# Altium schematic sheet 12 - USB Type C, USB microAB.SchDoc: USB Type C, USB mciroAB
size A3; PageSetup: Record=PageOptions¦CenterHorizontal=True¦CenterVertical=True¦PrintScale=0.70¦XCorrection=1.00¦YCorrection=1.00¦PrintKind=0¦BorderSize=5000000¦LeftOffset=0¦BottomOffset=0¦Orientation=2¦PaperLength=4200¦PaperWidth=2970¦Scale=100¦PaperSource=7¦PrintQuality=600¦MediaType=1¦DitherType=10¦PaperKind=A4¦PrintScaleMode=1; Author: Juan Anzola; SheetNumber: 12; SheetTotal: 17
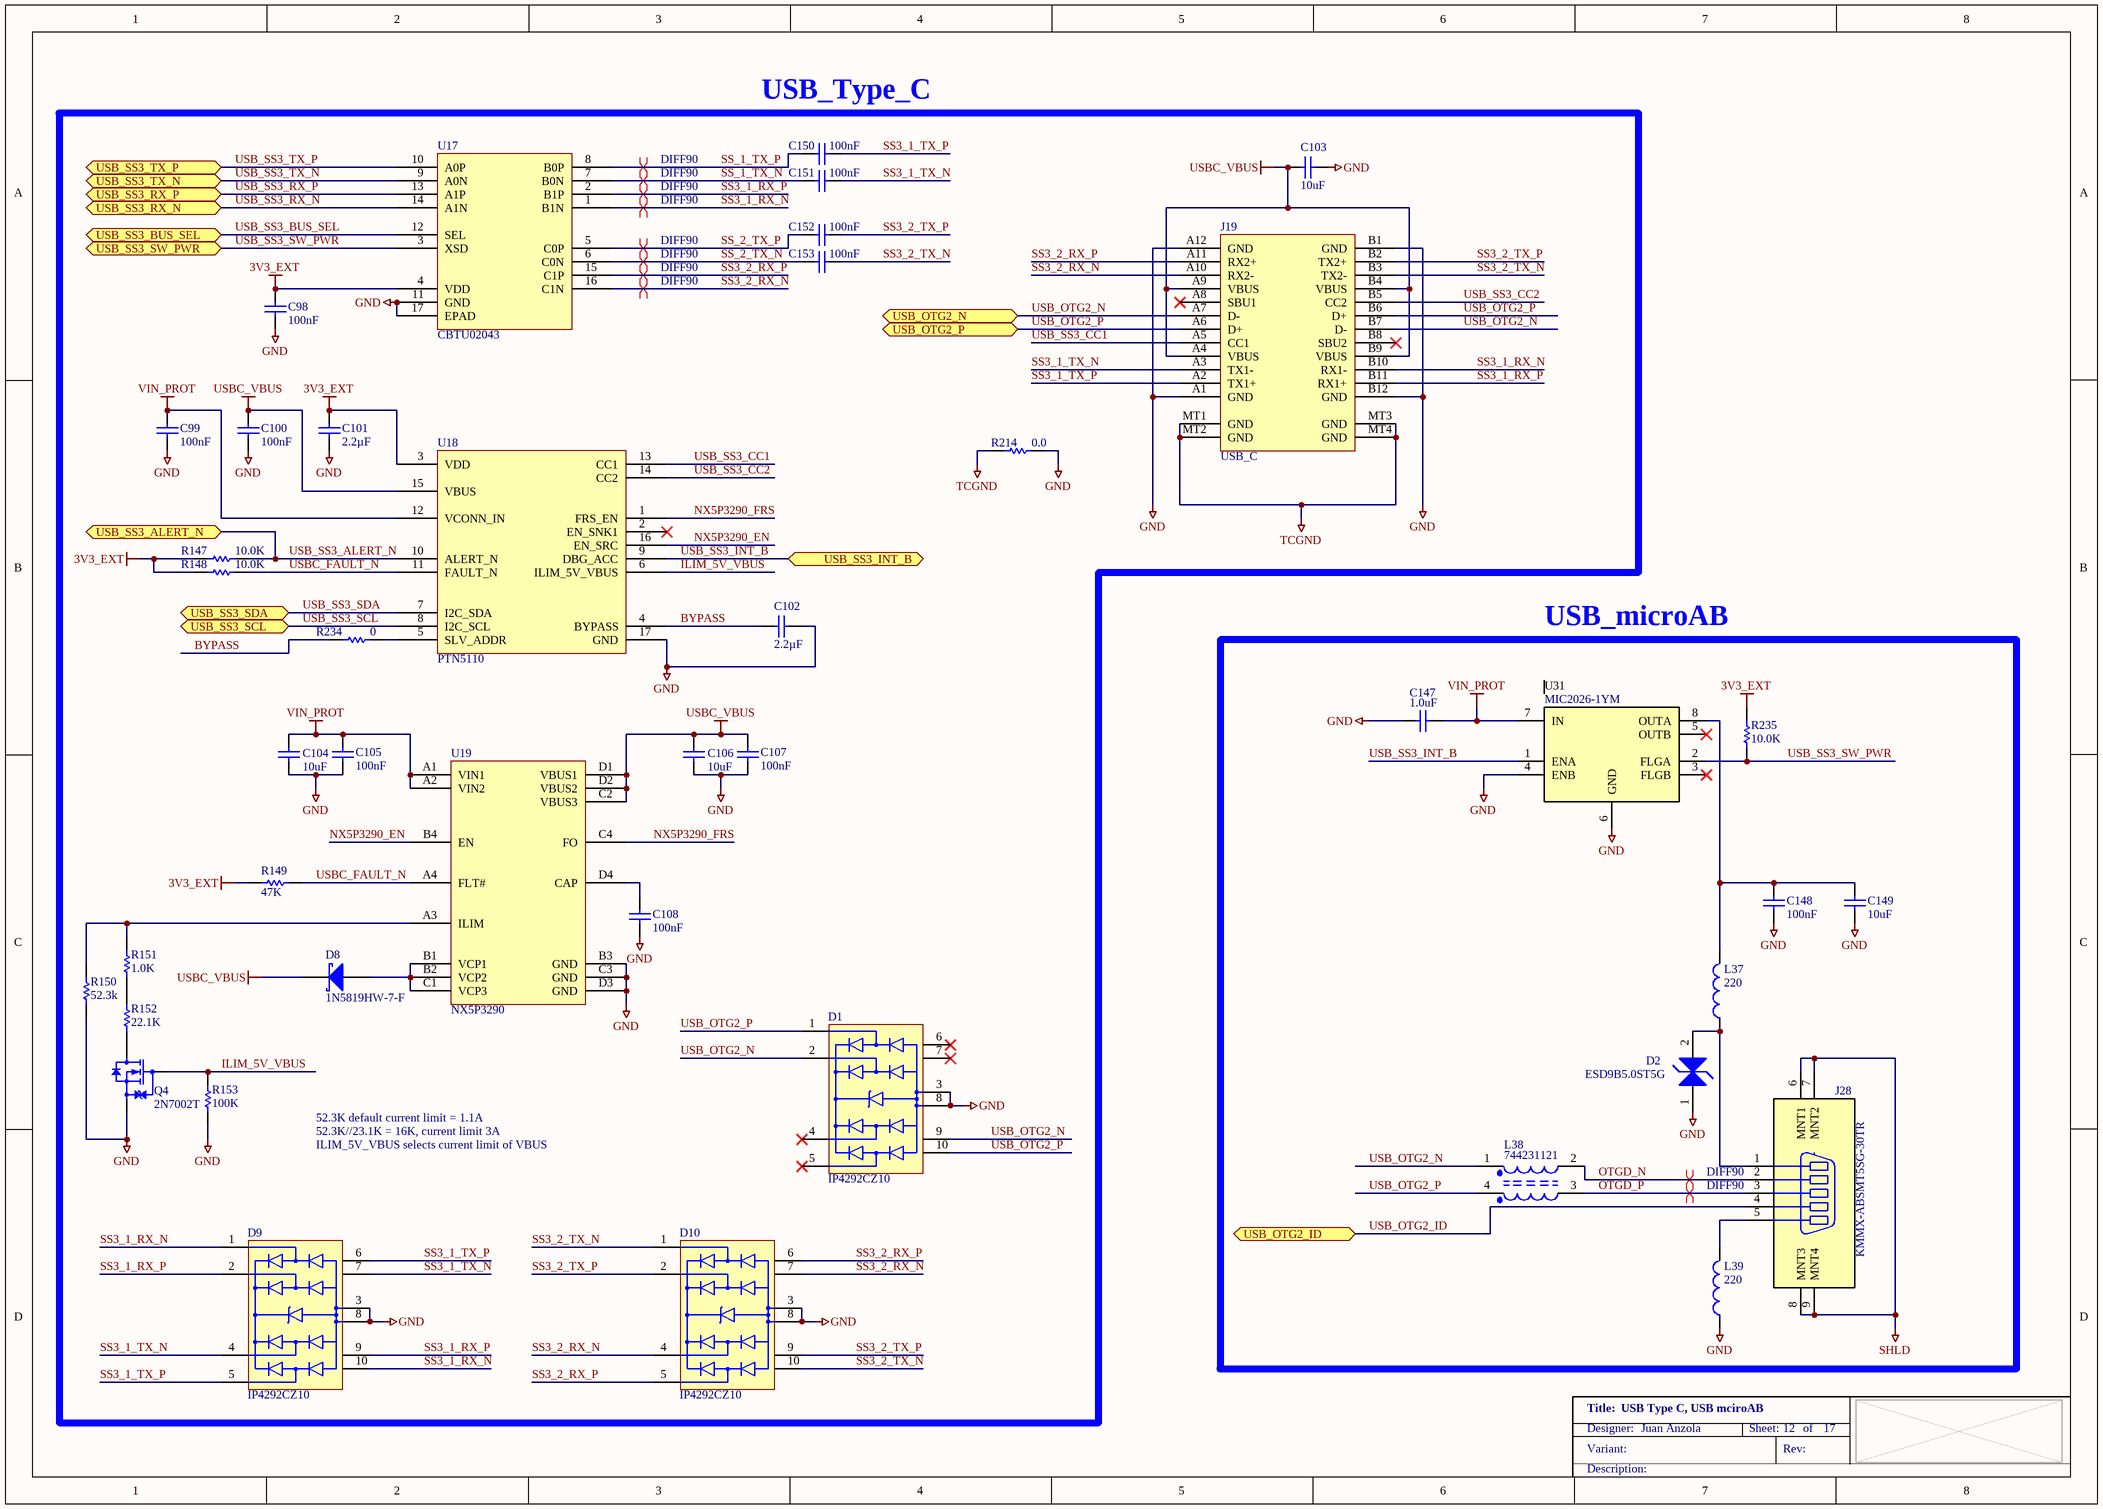
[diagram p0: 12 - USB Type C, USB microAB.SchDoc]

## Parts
C98  100nF  [CAPC1005X55N]
C99  100nF  [CAPC1005X55N]
C100  100nF  [CAPC1005X55N]
C101  2.2µF  [CAPC1005X55L]
C102  2.2µF  [CAPC1005X55L]
C103  10uF  [CAPC1005X55N]
C104  10uF  [CAPC1005X55N]
C105  100nF  [CAPC1005X55N]
C106  10uF  [CAPC1005X55N]
C107  100nF  [CAPC1005X55N]
C108  100nF  [CAPC1005X55N]
C147  1.0uF  [CAPC1005X55N]
C148  100nF  [CAPC1005X55N]
C149  10uF  [CAPC1005X55N]
C150  100nF  [CAPC1005X55N]
C151  100nF  [CAPC1005X55N]
C152  100nF  [CAPC1005X55N]
C153  100nF  [CAPC1005X55N]
D1  IP4292CZ10  [SON50P250X100X50-10N]
D2  ESD9B5.0ST5G  [SODFL1006X43N12]
D8  1N5819HW-7-F  [SOD3716X135N]
D9  IP4292CZ10  [SON50P250X100X50-10N]
D10  IP4292CZ10  [SON50P250X100X50-10N]
J19  USB_C  [MOLEX_201267-0005]
J28  KMMX-ABSMT5SG-30TR  [KYCON_KMMX-ABSMT5]
L37  220  [INDC2013X110N]
L38  744231121  [FIL_DLW21H]
L39  220  [INDC2013X110N]
Q4  2N7002T  [SOTFL50P160X80_GSD-3N]
R147  10.0K  [RESC1005X40N]
R148  10.0K  [RESC1005X40N]
R149  47K  [RESC1005X40N]
R150  52.3k  [RESC1005X40N]
R151  1.0K  [RESC1005X40N]
R152  22.1K  [RESC1005X40N]
R153  100K  [RESC1005X40N]
R214  0.0  [RESC2013X70N]
R234  0  [RESC1005X40N]
R235  10.0K  [RESC1005X40N]
U17  CBTU02043  [PQFN40P160X240X55-17T140X60N]
U18  PTN5110  [QFN40P260X260X40-17T100X110N]
U19  NX5P3290  [BGA16N50P4X4_205X205X59B32N]
U31  Manufacturer_Part_Number: MIC2026-1YM  [SOIC127P600X175-8N]  (hidden comment: MIC2026)

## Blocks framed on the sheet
USB_Type_C: C98-C108 C150-C153 D1 D8-D10 J19 Q4 R147-R153 R214 R234 U17-U19
USB_microAB: C147-C149 D2 J28 L37-L39 R235 U31

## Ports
USB_OTG2_ID (bidir), USB_OTG2_N (bidir), USB_OTG2_P (bidir), USB_SS3_ALERT_N (bidir), USB_SS3_BUS_SEL (bidir), USB_SS3_INT_B (bidir), USB_SS3_RX_N (bidir), USB_SS3_RX_P (bidir), USB_SS3_SCL (bidir), USB_SS3_SDA (bidir), USB_SS3_SW_PWR (bidir), USB_SS3_TX_N (bidir), USB_SS3_TX_P (bidir)

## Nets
3V3_EXT: C98.2 C101.2 R147.1 R148.1 R149.1 R235.2 U17.4(VDD) U18.3(VDD)
GND: C98.1 C99.1 C100.1 C101.1 C102.1 C103.1 C104.1 C105.1 C106.1 C107.1 C108.1 C147.1 C148.1 C149.1 D1.3(GND) D1.8(GND) D2.1 D9.3(GND) D9.8(GND) D10.3(GND) D10.8(GND) J19.A1(GND) J19.A12(GND) J19.B1(GND) J19.B12(GND) L39.1 Q4.S R150.1 R153.1 R214.2 U17.11(GND) U17.17(EPAD) U18.17(GND) U19.B3(GND) U19.C3(GND) U19.D3(GND) U31.4(ENB) U31.6(GND)
SHLD: J28.6(MNT1) J28.7(MNT2) J28.8(MNT3) J28.9(MNT4)
TCGND: J19.MT1(GND) J19.MT2(GND) J19.MT3(GND) J19.MT4(GND) R214.1
USBC_VBUS: C100.2 C103.2 C106.2 C107.2 D8.K J19.A4(VBUS) J19.A9(VBUS) J19.B4(VBUS) J19.B9(VBUS) U18.15(VBUS) U19.C2(VBUS3) U19.D1(VBUS1) U19.D2(VBUS2)
VIN_PROT: C99.2 C104.2 C105.2 C147.2 U18.12(VCONN_IN) U19.A1(VIN1) U19.A2(VIN2) U31.7(IN)
BYPASS: C102.2 R234.2 U18.4(BYPASS)
ILIM_5V_VBUS: Q4.G R153.2 U18.6(ILIM_5V_VBUS)
NX5P3290_EN: U18.16(EN_SRC) U19.B4(EN)
NX5P3290_FRS: U18.1(FRS_EN) U19.C4(FO)
OTGD_N: J28.2 L38.2
OTGD_P: J28.3 L38.3
SS3_1_RX_N: D9.1(CH1) D9.10(NC) J19.B10(RX1-) U17.1(B1N)
SS3_1_RX_P: D9.2(CH2) D9.9(NC) J19.B11(RX1+) U17.2(B1P)
SS3_1_TX_N: C151.2 D9.4(CH3) D9.7(NC) J19.A3(TX1-)
SS3_1_TX_P: C150.2 D9.5(CH4) D9.6(NC) J19.A2(TX1+)
SS3_2_RX_N: D10.4(CH3) D10.7(NC) J19.A10(RX2-) U17.16(C1N)
SS3_2_RX_P: D10.5(CH4) D10.6(NC) J19.A11(RX2+) U17.15(C1P)
SS3_2_TX_N: C153.2 D10.1(CH1) D10.10(NC) J19.B3(TX2-)
SS3_2_TX_P: C152.2 D10.2(CH2) D10.9(NC) J19.B2(TX2+)
SS_1_TX_N: C151.1 U17.7(B0N)
SS_1_TX_P: C150.1 U17.8(B0P)
SS_2_TX_N: C153.1 U17.6(C0N)
SS_2_TX_P: C152.1 U17.5(C0P)
USB_OTG2_ID: J28.4 ; port USB_OTG2_ID
USB_OTG2_N: D1.2(CH2) D1.9(NC) J19.A7(D-) J19.B7(D-) L38.1 ; port USB_OTG2_N
USB_OTG2_P: D1.1(CH1) D1.10(NC) J19.A6(D+) J19.B6(D+) L38.4 ; port USB_OTG2_P
USB_SS3_ALERT_N: R147.2 U18.10(ALERT_N) ; port USB_SS3_ALERT_N
USB_SS3_BUS_SEL: U17.12(SEL) ; port USB_SS3_BUS_SEL
USB_SS3_CC1: J19.A5(CC1) U18.13(CC1)
USB_SS3_CC2: J19.B5(CC2) U18.14(CC2)
USB_SS3_INT_B: U18.9(DBG_ACC) U31.1(ENA) ; port USB_SS3_INT_B
USB_SS3_RX_N: U17.14(A1N) ; port USB_SS3_RX_N
USB_SS3_RX_P: U17.13(A1P) ; port USB_SS3_RX_P
USB_SS3_SCL: U18.8(I2C_SCL) ; port USB_SS3_SCL
USB_SS3_SDA: U18.7(I2C_SDA) ; port USB_SS3_SDA
USB_SS3_SW_PWR: R235.1 U17.3(XSD) U31.2(FLGA) ; port USB_SS3_SW_PWR
USB_SS3_TX_N: U17.9(A0N) ; port USB_SS3_TX_N
USB_SS3_TX_P: U17.10(A0P) ; port USB_SS3_TX_P
USBC_FAULT_N: R148.2 R149.2 U18.11(FAULT_N) U19.A4(FLT#)
NetC108_2: C108.2 U19.D4(CAP)
NetC148_2: C148.2 C149.2 L37.2 U31.8(OUTA)
NetD2_2: D2.2 J28.1 L37.1
NetD8_A: D8.A U19.B1(VCP1) U19.B2(VCP2) U19.C1(VCP3)
NetJ28_5: J28.5 L39.2
NetQ4_D: Q4.D R152.1
NetR150_2: R150.2 R151.2 U19.A3(ILIM)
NetR151_1: R151.1 R152.2
NetR234_1: R234.1 U18.5(SLV_ADDR)

Not connected (* = marked no-connect by the designer): D1 4(CH3)* 5(CH4)* 6(NC)* 7(NC)*; J19 A8(SBU1)* B8(SBU2)*; U18 2(EN_SNK1)*; U31 3(FLGB)* 5(OUTB)*

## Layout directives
differential pair; net class DIFF90: OTGD_N, OTGD_P, SS3_1_RX_N, SS3_1_RX_P, SS3_2_RX_N, SS3_2_RX_P, SS_1_TX_N, SS_1_TX_P, SS_2_TX_N, SS_2_TX_P

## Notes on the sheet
- 52.3K default current limit = 1.1A
- 52.3K//23.1K = 16K, current limit 3A
- ILIM_5V_VBUS selects current limit of VBUS

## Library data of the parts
C98-C100 C105 C107 C108 C148 = 1000006: CAP 100nF 16V 10% X7R 0402; Part_Type: Capacitor; Manufacturer: Murata; Manufacturer_Part_Number: GRM155R71C104KA88D; Component_Life_Cycle_State: CAD Reviewed; Area: 0.95; Project: KITT; Tolerance: 10; Digi_PN: 14050552
C101 C102 = 1000970: CAP CER 2.2UF 6.3V 20% X5R 0402; Part_Type: Capacitor; Manufacturer: TDK Corporation; Manufacturer_Part_Number: C1005X5R0J225M050BC; Manufacturer_Alt_1: Taiyo Yuden; Manufacturer_Alt_1_Part_Number: JMK105BJ225MV-F; Note: 14050756 = Digi No. for GE WDNU; Digi_PN: 14050493; Component_Life_Cycle_State: Reviewed; Area: 0.5; Project: ConnectCore i.MX6 module; Tolerance: 20
C103 C104 C106 C149 = 1001168: CAP CER 10UF 10V 20% X5R 0402; Part_Type: Capacitor; Manufacturer: Samsung; Manufacturer_Part_Number: CL05A106MP5NUNC; Digi_PN: 14050689; Component_Life_Cycle_State: Reviewed; Area: 0.95; Project: CCWMX6_SBC board
C147 = 1001167: CAP CER 1UF 10V 10% X5R 0402; Part_Type: Capacitor; Manufacturer: Murata; Manufacturer_Part_Number: GRM155R61A105KE15D; Digi_PN: 14050399; Component_Life_Cycle_State: Reviewed; Area: 0.95; Project: CCWMX6_SBC board
C150-C153 = 1000918: CAP CER 0.1UF 50V 10% X7R 0402; Part_Type: Capacitor; Manufacturer: TDK Corporation; Manufacturer_Part_Number: C1005X7R1H104K050BB; Digi_PN: 14050715; Component_Life_Cycle_State: Reviewed; Area: 0,95; Project: DTM3.0
D1 D9 D10 = 1002593: TVS DIODE 5.5V 4V 10DFN; Part_Type: Circuit Protection; Manufacturer: Phillips NXP; Digi_PN: 17000143; Component_Life_Cycle_State: Created; Area: 7,24; Project: DIGI CC8X SOM
D2 = 1001264: TVS DIODE 5VWM SOD923; Part_Type: Diodes; Manufacturer: On Semiconductor; Digi_PN: 17050587; Component_Life_Cycle_State: Reviewed; Area: 1.5; Project: CCWMX6_SBC board
D8 = 1000231: DIODE SCHOTTKY 40V 1A SOD123; Part_Type: Diodes; Manufacturer: Diodes, Inc.; Digi_PN: 17000146; Component_Life_Cycle_State: Proven; Area: 8.28; Project: Adjustable Foundation
J19 = 1002675: USB 3.1 SHIELDED I/O RECP TYPE C GEN2; Part_Type: Connector; Manufacturer: Molex; Manufacturer_Part_Number: 201267-0005; Digi_PN: 18000775; Component_Life_Cycle_State: Created; Area: 86.57; Project: DIGI CC8X SOM
J28 = 1001117: CONN RECEPT MICRO-USB TYPE AB R/A; Part_Type: Connector; Manufacturer: KYCON; Digi_PN: 18000401; Component_Life_Cycle_State: Reviewed; Area: 40; Project: CCWMX6_SBC board
L37 L39 = 1001174: FERRITE BEAD 220 OHM 2.0A 0805; Manufacturer: Wurth Electronics Inc; Manufacturer_Part_Number: 742792022; Digi_PN: 21000146; Component_Life_Cycle_State: Reviewed; Area: 4.24; Project: CCWMX6_SBC board
L38 = 1001173: CHOKE COM MODE 120 OHM .37A; Part_Type: Inductor; Manufacturer: Wurth Electronics Inc; Digi_PN: 21000143; Component_Life_Cycle_State: Reviewed; Area: 2.4; Project: CCWMX6_SBC board
Q4 = 1000715: MOSFET N-CH 60V 115MA SOT-523F; Part_Type: Transistor; Manufacturer: Fairchild Semiconductor; Digi_PN: 17050797; Component_Life_Cycle_State: CAD Reviewed; Area: 3.06; Project: SmartMeter2; Note: 17050841 = Digi No. for GE WDNU
R147 R148 R235 = 1000537: RES 10.0K OHM 1/10W 1% 0402 SMD; Part_Type: Resistor; Manufacturer: Panasonic - ECG; Manufacturer_Part_Number: ERJ-2RKF1002X; Component_Life_Cycle_State: CAD Reviewed; Area: 0.95; Project: KITT; Power_WV_SRF: 100; Digi_PN: 13051084
R149 = 1001155: RES 47.0K OHM 1/16W 1% 0402 SMD; Part_Type: Resistor; Manufacturer: Vishay Dale; Manufacturer_Part_Number: CRCW040247K0FKED; Digi_PN: 13050646; Component_Life_Cycle_State: Reviewed; Area: 0,95; Project: CCWMX6_SBC board
R150 = 1000170: RES 52.3K OHM 1/10W 1% 0402 SMD; Part_Type: Resistor; Manufacturer: Panasonic - ECG; Manufacturer_Part_Number: ERJ-2RKF5232X; Digi_PN: 13000085; Component_Life_Cycle_State: Reviewed; Area: 0.95; Project: USB UART to USB Transceiver; Power_WV_SRF: 10
R151 = 1000079: RES 1.00K OHM 1/10W 1% 0402 SMD; Part_Type: Resistor; Manufacturer: Panasonic - ECG; Manufacturer_Part_Number: ERJ-2RKF1001X; Digi_PN: 13051085; Component_Life_Cycle_State: Proven; Area: 0,95; Project: Adjustable Foundation; Power_WV_SRF: 10
R152 = 1001149: RES 22.1K OHM 1/16W 1% 0402 SMD; Part_Type: Resistor; Manufacturer: Vishay Dale; Manufacturer_Part_Number: CRCW040222K1FKED; Digi_PN: 13050450; Component_Life_Cycle_State: Reviewed; Area: 0,95; Project: CCWMX6_SBC board; Power_WV_SRF: 0,063; Tolerance: ±100ppm/°C
R153 = 1000480: RES 100K OHM 1/10W 1% 0402 SMD; Part_Type: Resistor; Manufacturer: Panasonic - ECG; Manufacturer_Part_Number: ERJ-2RKF1003X; Digi_PN: 13051063; Component_Life_Cycle_State: CAD Reviewed; Area: 0.95; Project: KITT; Power_WV_SRF: 100
R214 = 1001557: RES 0.0 OHM 1/8W JUMP 0805 SMD; Part_Type: Resistor; Manufacturer: Yageo; Manufacturer_Part_Number: RC0805JR-070RL; Note: 13051095 = Digi No. for GE WDNU; Digi_PN: TR00037; Component_Life_Cycle_State: Reviewed; Area: 5,8; Project: WDNU-II; Power_WV_SRF: 125
R234 = 1000076: RES 0.0 OHM 1/10W 0402 SMD; Part_Type: Resistor; Manufacturer: Panasonic - ECG; Manufacturer_Part_Number: ERJ-2GE0R00X; Digi_PN: 13050387; Component_Life_Cycle_State: Proven; Area: 0,95; Project: Adjustable Foundation; Power_WV_SRF: 10
U17 = 1002584: IC DIFF SWITCH 2:1 HUQFN16; Manufacturer: NXP Semiconductors; Digi_PN: 16000124; Component_Life_Cycle_State: Reviewed; Area: 6.09; Project: DIGI CC8X SOM
U18 = 1002585: IC USB PD TCPC PHY HX2QFN16; Manufacturer: NXP Semiconductors; Digi_PN: 16000125; Component_Life_Cycle_State: Reviewed; Area: 14.75; Project: DIGI CC8X SOM
U19 = 1002586: IC USB POWER SWITCH 16WLCSP; Manufacturer: NXP Semiconductors; Digi_PN: 16000126; Component_Life_Cycle_State: Reviewed; Area: 6.76; Project: DIGI CC8X SOM
U31 = 1001143: IC SW DISTRIBUTION 2CHAN 8SOIC; Manufacturer: Micrel; Digi_PN: 16051879; Component_Life_Cycle_State: Reviewed; Area: 29.58; Project: CCWMX6_SBC board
